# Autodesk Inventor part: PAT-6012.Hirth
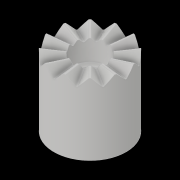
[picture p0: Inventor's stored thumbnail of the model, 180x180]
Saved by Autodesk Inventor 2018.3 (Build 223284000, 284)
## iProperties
Created: 2020-03
Part Number: PAT-6012.Hirth
Material: Generic
Document SubType Name: Modeling
Designer: Th. Mörgeli
Mass: 17.6706 g
Surface Area: 48.4307 cm^2
Volume: 17.6706 cm^3
Density: 1 g/cm^3
Appearance: Default
Author: Th. Mörgeli
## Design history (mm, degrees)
sketch "Sketch2"
  geometry: L1 (-7, 1.963)-(-7, -8); L2 (-7, -8)-(-6, -9); L3 (-6, -9)-(-6, -15); L4 (-6, -15)-(0, -17.184); L5 (0, -17.184)-(0, -28); L6 (0, -28)-(-15, -28); L7 (-15, -28)-(-15, 1.963); L8 (-15, 1.963)-(-7, 1.963); 1 further point
  constraints: 16 end point, 2 parallel, 2 perpendicular, 1 horizontal, 1 point on line, 1 vertical
  dimensions: "d8" = 14 diameter of L1 L5 (= Gewindebohrungsdurchmesser); "d10" = 12 diameter of L3 L5 (= Bohrungsdurchmesser); "d11" = 8 vertical distance of L1.end point (0, 0) (= Gewindetiefe); "d12" = 15 vertical distance of L3.end point (0, 0) (= Bohrungstiefe); "d14" = 45 deg angle of L1 L2; "d15" = 70 deg angle of L5 L4; "d16" = 1.9635 distance from line of point (0, 0) L8 (= 0.5 x Zahnhoehe); "d17" = 30 diameter of L7 L5 (= Aussendurchmesser); "d18" = 28 distance from line of point (0, 0) L6 (= Laenge)
revolve "Grundkoerper" sketch "Sketch2" stored, may be unused: angle "d19" = 90 deg
sketch "SKIZZE Ebene"
  geometry: L1 (0, 0)-(-15, 0); L2 (-15, 0)-(-15, -1.963); L3 (-15, -1.963)-(0, 0); L4 (-15, -1.963)-(-15.257, 0); 1 further point
  constraints: 8 end point, 2 perpendicular, 1 coincident, 1 horizontal, 1 point on line
  dimensions: "d20" = 15 distance of L1.start L1.end (= 0.5 x Aussendurchmesser); "d21" = 7.4576 deg angle of L1 L3 (= Neigungswinkel)
node "EBENE"
sketch "Sketch4"
  geometry: L1 (0, 0)-(7.854, 7.854); L2 (7.854, 7.854)-(7.854, -7.854); L3 (7.854, -7.854)-(0, 0); L4 (0, 0)-(7.854, 0)
  constraints: 8 end point, 1 midpoint, 1 perpendicular, 1 vertical, 1 other
  dimensions: "d23" = 90 deg angle of L1 L3 (= Flankenwinkel); "d24" = 7.85398 distance of L1.start L4.end (= 2 x Zahnhoehe)
extrude "Zahnluecke" cut sketch "Sketch4" extent not by distance; stored distance "d25" = 10; taper "d26" = 0 deg
fillet "Fussradius" dims "d27" = 0.5 (= Fussradius)
pattern_circular "MUSTER Zahn" dims angle "d29" = 360 deg
chamfer "Kopfspiel" distance "d31" = 0.49497 (= 0.707107 x Kopfflaeche); stored, may be unused: second distance "d32" = 2, angle "d33" = 45 deg
body "Solid2"
other parameters: "Aussendurchmesser" = 30 [user parameter; used in 4 equation terms], "Laenge" = 28 [user parameter; used in 1 equation term], "Gewindebohrungsdurchmesser" = 14 [user parameter; used in 1 equation term], "Gewindetiefe" = 8 [user parameter; used in 1 equation term], "Bohrungsdurchmesser" = 12 [user parameter; used in 1 equation term], "Bohrungstiefe" = 15 [user parameter; used in 1 equation term], "Zahnhoehe" = 22.5 deg (computed from Aussendurchmesser, Zaehnezahl, Flankenwinkel) [user parameter; used in 3 equation terms], "Neigungswinkel" = 7.4576 deg (computed from Aussendurchmesser, Zahnhoehe) [user parameter; used in 1 equation term], "d22" = 90 deg, "Flankenwinkel" = 90 deg [user parameter; used in 2 equation terms], "Fussradius" = 0.5 [user parameter; used in 1 equation term], "Kopfflaeche" = 0.7 [user parameter; used in 1 equation term]
